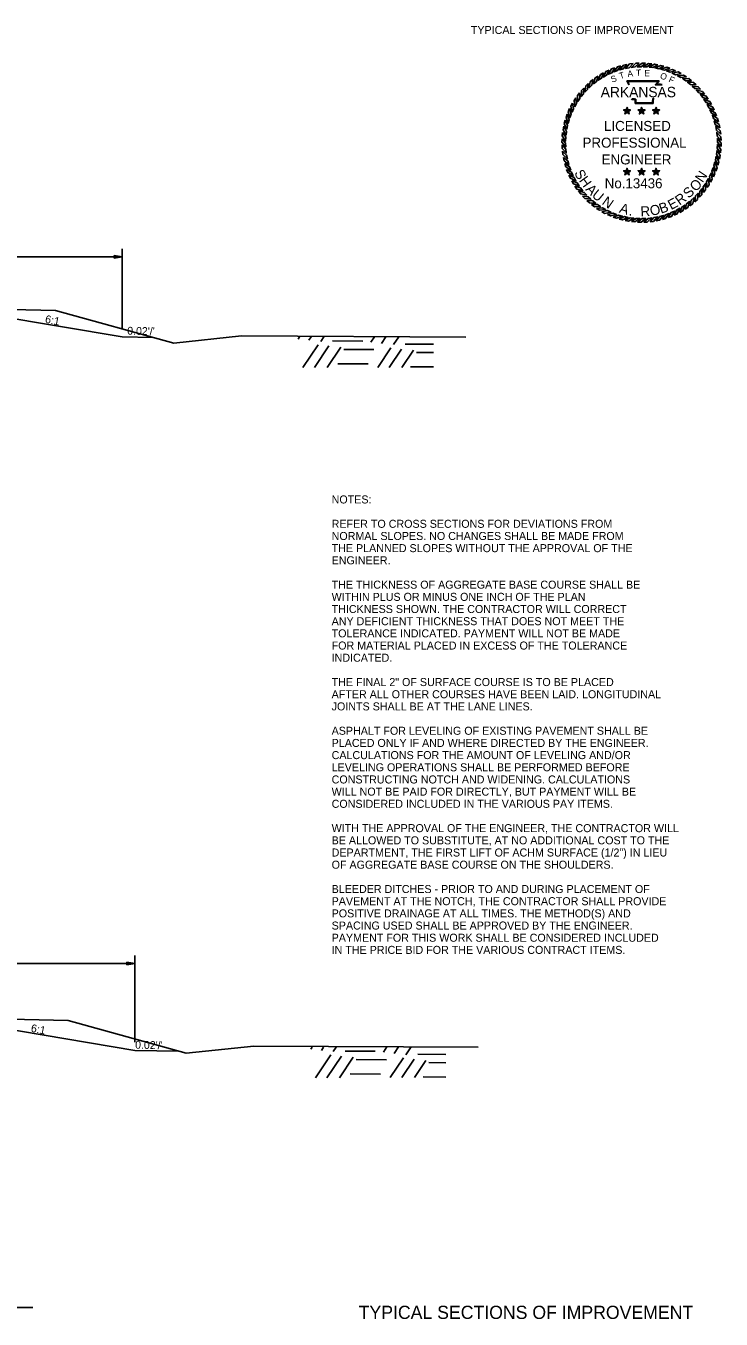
# Model space of a CAD drawing. Extents: x 1398565 to 1398920, y 1968324 to 1968581.
# Drawn here: x 1398667.6 to 1398719.8, y 1968480.4 to 1968577.4 of the extents above; entities that cross this region are included whole.
import ezdxf

# ---------------------------------------------------------------- set-up
doc = ezdxf.new("R2010")
doc.units = 0
for name, color, linetype in [('1', 7, 'Continuous'), ('10', 7, 'Continuous'), ('19', 7, 'Continuous'), ('42', 7, 'Continuous'), ('9', 7, 'Continuous'), ('G-ANNO-SYMB', 7, 'Continuous')]:
    doc.layers.add(name, color=color, linetype=linetype)

msp = doc.modelspace()

# ---------------------------------------------------------------- linework, layer by layer
at = {"layer": '19'}
for p, q in [((1398674.859, 1968554.677), (1398674.859, 1968560.664)), ((1398652.859, 1968560.064), (1398674.859, 1968560.064)), ((1398674.259, 1968559.959), (1398674.259, 1968560.169)), ((1398674.259, 1968560.169), (1398674.859, 1968560.064)), ((1398674.259, 1968560.114), (1398674.699, 1968560.079)), ((1398674.859, 1968560.064), (1398674.259, 1968559.959)), ((1398674.699, 1968560.049), (1398674.259, 1968560.009)), ((1398660.859, 1968556.402), (1398674.859, 1968554.068)), ((1398677.176, 1968554.022), (1398674.859, 1968554.068)), ((1398675.195, 1968506.994), (1398675.195, 1968507.204)), ((1398675.195, 1968507.204), (1398675.795, 1968507.099)), ((1398675.795, 1968501.198), (1398675.795, 1968507.699)), ((1398653.795, 1968507.099), (1398675.795, 1968507.099)), ((1398675.195, 1968507.149), (1398675.635, 1968507.114)), ((1398675.795, 1968507.099), (1398675.195, 1968506.994)), ((1398675.635, 1968507.084), (1398675.195, 1968507.044)), ((1398659.795, 1968503.256), (1398675.795, 1968500.59)), ((1398679.094, 1968500.524), (1398675.795, 1968500.59)), ((1398639.176, 1968481.304), (1398668.156, 1968481.304))]:
    msp.add_line(p, q, dxfattribs=at)
at = {"layer": '42'}
for points in [[(1398652.859, 1968556.515), (1398660.944, 1968556.232), (1398669.859, 1968556.055), (1398678.715, 1968553.595), (1398683.795, 1968554.136), (1398700.612, 1968554.047)], [(1398653.795, 1968503.29), (1398659.88, 1968503.086), (1398670.795, 1968502.83), (1398679.65, 1968500.369), (1398684.731, 1968500.911), (1398701.547, 1968500.822)]]:
    msp.add_lwpolyline(points, dxfattribs=at)
at = {"layer": '9'}
for p, q in [((1398688.049, 1968553.904), (1398688.153, 1968554.058)), ((1398688.847, 1968553.813), (1398689.013, 1968554.06)), ((1398689.737, 1968553.722), (1398689.965, 1968554.061)), ((1398690.627, 1968553.76), (1398692.889, 1968553.746)), ((1398693.501, 1968553.673), (1398693.766, 1968554.068)), ((1398694.298, 1968553.581), (1398694.626, 1968554.069)), ((1398695.188, 1968553.49), (1398695.579, 1968554.071)), ((1398688.399, 1968551.764), (1398689.552, 1968553.48)), ((1398689.258, 1968551.766), (1398690.349, 1968553.389)), ((1398690.211, 1968551.768), (1398691.239, 1968553.298)), ((1398691.462, 1968553.131), (1398693.724, 1968553.116)), ((1398694.012, 1968551.774), (1398695.003, 1968553.249)), ((1398694.872, 1968551.776), (1398695.801, 1968553.157)), ((1398695.824, 1968551.777), (1398696.691, 1968553.066)), ((1398696.078, 1968553.529), (1398698.184, 1968553.515)), ((1398696.913, 1968552.899), (1398698.185, 1968552.891)), ((1398691.019, 1968552.055), (1398693.281, 1968552.04)), ((1398696.47, 1968551.823), (1398698.187, 1968551.812)), ((1398688.985, 1968500.679), (1398689.089, 1968500.833)), ((1398689.782, 1968500.587), (1398689.948, 1968500.834)), ((1398690.673, 1968500.496), (1398690.901, 1968500.836)), ((1398691.562, 1968500.535), (1398693.824, 1968500.52)), ((1398694.436, 1968500.447), (1398694.702, 1968500.842)), ((1398695.234, 1968500.356), (1398695.562, 1968500.844)), ((1398696.124, 1968500.264), (1398696.514, 1968500.846)), ((1398689.334, 1968498.539), (1398690.488, 1968500.255)), ((1398690.194, 1968498.54), (1398691.285, 1968500.163)), ((1398691.146, 1968498.542), (1398692.175, 1968500.072)), ((1398692.398, 1968499.906), (1398694.66, 1968499.891)), ((1398694.948, 1968498.549), (1398695.939, 1968500.023)), ((1398695.807, 1968498.55), (1398696.736, 1968499.932)), ((1398696.76, 1968498.552), (1398697.626, 1968499.84)), ((1398697.014, 1968500.303), (1398699.119, 1968500.29)), ((1398697.849, 1968499.674), (1398699.121, 1968499.666)), ((1398691.955, 1968498.829), (1398694.217, 1968498.815)), ((1398697.406, 1968498.597), (1398699.122, 1968498.586))]:
    msp.add_line(p, q, dxfattribs=at)
at = {"layer": 'G-ANNO-SYMB'}
for points in [[(1398711.35, 1968574.067), (1398711.118, 1968573.957), (1398710.925, 1968573.543), (1398711.168, 1968573.676)], [(1398711.784, 1968574.242), (1398711.545, 1968574.15), (1398711.32, 1968573.752), (1398711.572, 1968573.866)], [(1398712.231, 1968574.382), (1398711.985, 1968574.309), (1398711.73, 1968573.93), (1398711.99, 1968574.024)], [(1398712.688, 1968574.486), (1398712.437, 1968574.433), (1398712.152, 1968574.076), (1398712.42, 1968574.149)], [(1398713.152, 1968574.555), (1398712.897, 1968574.522), (1398712.585, 1968574.187), (1398712.857, 1968574.239)], [(1398713.619, 1968574.586), (1398713.363, 1968574.573), (1398713.026, 1968574.264), (1398713.301, 1968574.295)], [(1398714.087, 1968574.581), (1398713.831, 1968574.589), (1398713.471, 1968574.307), (1398713.748, 1968574.316)], [(1398714.554, 1968574.54), (1398714.299, 1968574.567), (1398713.917, 1968574.315), (1398714.194, 1968574.302)], [(1398715.016, 1968574.461), (1398714.764, 1968574.509), (1398714.364, 1968574.287), (1398714.639, 1968574.252)], [(1398715.47, 1968574.347), (1398715.222, 1968574.414), (1398714.806, 1968574.224), (1398715.078, 1968574.168)], [(1398715.914, 1968574.198), (1398715.672, 1968574.284), (1398715.243, 1968574.127), (1398715.509, 1968574.05)], [(1398716.345, 1968574.014), (1398716.111, 1968574.119), (1398715.67, 1968573.996), (1398715.929, 1968573.898)], [(1398710.146, 1968573.347), (1398709.946, 1968573.186), (1398709.855, 1968572.738), (1398710.06, 1968572.925)], [(1398710.528, 1968573.618), (1398710.316, 1968573.474), (1398710.19, 1968573.034), (1398710.409, 1968573.204)], [(1398710.93, 1968573.859), (1398710.708, 1968573.731), (1398710.547, 1968573.303), (1398710.779, 1968573.455)], [(1398716.76, 1968573.797), (1398716.535, 1968573.92), (1398716.086, 1968573.832), (1398716.337, 1968573.714)], [(1398717.157, 1968573.548), (1398716.942, 1968573.688), (1398716.488, 1968573.636), (1398716.728, 1968573.499)], [(1398717.533, 1968573.268), (1398717.33, 1968573.425), (1398716.873, 1968573.409), (1398717.102, 1968573.253)], [(1398717.886, 1968572.96), (1398717.695, 1968573.132), (1398717.239, 1968573.152), (1398717.455, 1968572.979)], [(1398709.144, 1968572.366), (1398708.987, 1968572.163), (1398709.003, 1968571.706), (1398709.159, 1968571.935)], [(1398709.452, 1968572.719), (1398709.28, 1968572.529), (1398709.26, 1968572.072), (1398709.433, 1968572.288)], [(1398709.787, 1968573.047), (1398709.6, 1968572.871), (1398709.545, 1968572.417), (1398709.734, 1968572.619)], [(1398718.213, 1968572.625), (1398718.037, 1968572.812), (1398717.583, 1968572.868), (1398717.785, 1968572.678)], [(1398718.514, 1968572.266), (1398718.353, 1968572.466), (1398717.905, 1968572.557), (1398718.091, 1968572.352)], [(1398718.785, 1968571.884), (1398718.64, 1968572.096), (1398718.201, 1968572.222), (1398718.371, 1968572.003)], [(1398708.398, 1968571.178), (1398708.294, 1968570.944), (1398708.416, 1968570.503), (1398708.514, 1968570.763)], [(1398708.616, 1968571.593), (1398708.493, 1968571.368), (1398708.58, 1968570.919), (1398708.698, 1968571.17)], [(1398708.865, 1968571.99), (1398708.724, 1968571.775), (1398708.776, 1968571.321), (1398708.913, 1968571.562)], [(1398712.698, 1968570.998), (1398712.76, 1968571.083), (1398712.698, 1968571.271), (1398712.637, 1968571.083)], [(1398713.789, 1968570.998), (1398713.851, 1968571.083), (1398713.789, 1968571.271), (1398713.728, 1968571.083)], [(1398714.88, 1968570.998), (1398714.942, 1968571.083), (1398714.88, 1968571.271), (1398714.819, 1968571.083)], [(1398719.026, 1968571.482), (1398718.898, 1968571.705), (1398718.469, 1968571.865), (1398718.622, 1968571.633)], [(1398719.234, 1968571.062), (1398719.124, 1968571.294), (1398718.709, 1968571.487), (1398718.843, 1968571.245)], [(1398708.065, 1968570.303), (1398707.998, 1968570.056), (1398708.188, 1968569.64), (1398708.244, 1968569.911)], [(1398708.215, 1968570.747), (1398708.128, 1968570.506), (1398708.285, 1968570.076), (1398708.362, 1968570.342)], [(1398712.698, 1968570.998), (1398712.637, 1968571.083), (1398712.439, 1968571.083), (1398712.599, 1968570.966)], [(1398712.698, 1968570.998), (1398712.599, 1968570.966), (1398712.538, 1968570.778), (1398712.698, 1968570.894)], [(1398712.698, 1968570.998), (1398712.798, 1968570.966), (1398712.958, 1968571.083), (1398712.76, 1968571.083)], [(1398712.698, 1968570.998), (1398712.698, 1968570.894), (1398712.859, 1968570.778), (1398712.798, 1968570.966)], [(1398713.789, 1968570.998), (1398713.728, 1968571.083), (1398713.53, 1968571.083), (1398713.69, 1968570.966)], [(1398713.789, 1968570.998), (1398713.69, 1968570.966), (1398713.629, 1968570.778), (1398713.789, 1968570.894)], [(1398713.789, 1968570.998), (1398713.888, 1968570.966), (1398714.049, 1968571.083), (1398713.851, 1968571.083)], [(1398713.789, 1968570.998), (1398713.789, 1968570.894), (1398713.95, 1968570.778), (1398713.888, 1968570.966)], [(1398714.88, 1968570.998), (1398714.819, 1968571.083), (1398714.621, 1968571.083), (1398714.781, 1968570.966)], [(1398714.88, 1968570.998), (1398714.781, 1968570.966), (1398714.72, 1968570.778), (1398714.88, 1968570.894)], [(1398714.88, 1968570.998), (1398714.979, 1968570.966), (1398715.14, 1968571.083), (1398714.942, 1968571.083)], [(1398714.88, 1968570.998), (1398714.88, 1968570.894), (1398715.041, 1968570.778), (1398714.979, 1968570.966)], [(1398719.408, 1968570.628), (1398719.317, 1968570.867), (1398718.919, 1968571.093), (1398719.033, 1968570.84)], [(1398719.548, 1968570.181), (1398719.476, 1968570.427), (1398719.097, 1968570.683), (1398719.191, 1968570.422)], [(1398719.653, 1968569.724), (1398719.6, 1968569.975), (1398719.242, 1968570.26), (1398719.315, 1968569.992)], [(1398707.873, 1968569.387), (1398707.845, 1968569.132), (1398708.098, 1968568.751), (1398708.111, 1968569.028)], [(1398707.951, 1968569.849), (1398707.904, 1968569.597), (1398708.125, 1968569.197), (1398708.16, 1968569.472)], [(1398719.721, 1968569.261), (1398719.688, 1968569.515), (1398719.354, 1968569.827), (1398719.406, 1968569.555)], [(1398719.753, 1968568.793), (1398719.74, 1968569.049), (1398719.431, 1968569.387), (1398719.462, 1968569.111)], [(1398707.831, 1968568.921), (1398707.824, 1968568.664), (1398708.105, 1968568.304), (1398708.096, 1968568.581)], [(1398707.826, 1968568.452), (1398707.839, 1968568.196), (1398708.148, 1968567.859), (1398708.117, 1968568.134)], [(1398719.706, 1968567.858), (1398719.734, 1968568.113), (1398719.481, 1968568.495), (1398719.468, 1968568.218)], [(1398719.748, 1968568.325), (1398719.755, 1968568.581), (1398719.474, 1968568.942), (1398719.482, 1968568.665)], [(1398707.858, 1968567.985), (1398707.891, 1968567.73), (1398708.225, 1968567.419), (1398708.173, 1968567.691)], [(1398707.926, 1968567.521), (1398707.979, 1968567.27), (1398708.337, 1968566.986), (1398708.263, 1968567.253)], [(1398719.514, 1968566.942), (1398719.581, 1968567.19), (1398719.391, 1968567.606), (1398719.335, 1968567.334)], [(1398719.628, 1968567.396), (1398719.675, 1968567.649), (1398719.454, 1968568.048), (1398719.419, 1968567.773)], [(1398708.03, 1968567.065), (1398708.103, 1968566.819), (1398708.482, 1968566.563), (1398708.388, 1968566.824)], [(1398708.17, 1968566.618), (1398708.262, 1968566.378), (1398708.66, 1968566.153), (1398708.546, 1968566.405)], [(1398712.698, 1968566.43), (1398712.637, 1968566.514), (1398712.439, 1968566.514), (1398712.599, 1968566.398)], [(1398712.698, 1968566.43), (1398712.599, 1968566.398), (1398712.538, 1968566.21), (1398712.698, 1968566.326)], [(1398712.698, 1968566.43), (1398712.76, 1968566.514), (1398712.698, 1968566.703), (1398712.637, 1968566.514)], [(1398712.698, 1968566.43), (1398712.798, 1968566.398), (1398712.958, 1968566.514), (1398712.76, 1968566.514)], [(1398712.698, 1968566.43), (1398712.698, 1968566.326), (1398712.859, 1968566.21), (1398712.798, 1968566.398)], [(1398713.789, 1968566.43), (1398713.728, 1968566.514), (1398713.53, 1968566.514), (1398713.69, 1968566.398)], [(1398713.789, 1968566.43), (1398713.69, 1968566.398), (1398713.629, 1968566.21), (1398713.789, 1968566.326)], [(1398713.789, 1968566.43), (1398713.851, 1968566.514), (1398713.789, 1968566.703), (1398713.728, 1968566.514)], [(1398713.789, 1968566.43), (1398713.888, 1968566.398), (1398714.049, 1968566.514), (1398713.851, 1968566.514)], [(1398713.789, 1968566.43), (1398713.789, 1968566.326), (1398713.95, 1968566.21), (1398713.888, 1968566.398)], [(1398714.88, 1968566.43), (1398714.819, 1968566.514), (1398714.621, 1968566.514), (1398714.781, 1968566.398)], [(1398714.88, 1968566.43), (1398714.781, 1968566.398), (1398714.72, 1968566.21), (1398714.88, 1968566.326)], [(1398714.88, 1968566.43), (1398714.942, 1968566.514), (1398714.88, 1968566.703), (1398714.819, 1968566.514)], [(1398714.88, 1968566.43), (1398714.979, 1968566.398), (1398715.14, 1968566.514), (1398714.942, 1968566.514)], [(1398714.88, 1968566.43), (1398714.88, 1968566.326), (1398715.041, 1968566.21), (1398714.979, 1968566.398)], [(1398718.963, 1968565.652), (1398719.086, 1968565.877), (1398718.999, 1968566.326), (1398718.881, 1968566.075)], [(1398719.18, 1968566.067), (1398719.285, 1968566.301), (1398719.163, 1968566.742), (1398719.065, 1968566.483)], [(1398719.364, 1968566.498), (1398719.45, 1968566.74), (1398719.294, 1968567.169), (1398719.217, 1968566.903)], [(1398708.345, 1968566.183), (1398708.455, 1968565.951), (1398708.869, 1968565.758), (1398708.736, 1968566.001)], [(1398708.553, 1968565.763), (1398708.681, 1968565.541), (1398709.109, 1968565.381), (1398708.957, 1968565.612)], [(1398708.794, 1968565.361), (1398708.939, 1968565.15), (1398709.378, 1968565.024), (1398709.208, 1968565.243)], [(1398718.435, 1968564.879), (1398718.591, 1968565.083), (1398718.576, 1968565.54), (1398718.42, 1968565.31)], [(1398718.714, 1968565.255), (1398718.854, 1968565.47), (1398718.803, 1968565.925), (1398718.665, 1968565.684)], [(1398709.065, 1968564.98), (1398709.226, 1968564.78), (1398709.674, 1968564.689), (1398709.488, 1968564.894)], [(1398709.365, 1968564.62), (1398709.542, 1968564.434), (1398709.995, 1968564.378), (1398709.793, 1968564.568)], [(1398717.433, 1968563.898), (1398717.632, 1968564.059), (1398717.724, 1968564.507), (1398717.519, 1968564.321)], [(1398717.792, 1968564.199), (1398717.979, 1968564.375), (1398718.034, 1968564.829), (1398717.845, 1968564.627)], [(1398718.127, 1968564.526), (1398718.299, 1968564.717), (1398718.319, 1968565.174), (1398718.146, 1968564.957)], [(1398709.693, 1968564.285), (1398709.883, 1968564.113), (1398710.34, 1968564.093), (1398710.124, 1968564.267)], [(1398710.046, 1968563.977), (1398710.249, 1968563.821), (1398710.706, 1968563.837), (1398710.477, 1968563.992)], [(1398710.422, 1968563.698), (1398710.637, 1968563.558), (1398711.091, 1968563.61), (1398710.85, 1968563.747)], [(1398710.819, 1968563.449), (1398711.044, 1968563.326), (1398711.493, 1968563.413), (1398711.242, 1968563.531)], [(1398715.794, 1968563.004), (1398716.034, 1968563.095), (1398716.259, 1968563.493), (1398716.007, 1968563.379)], [(1398716.229, 1968563.178), (1398716.461, 1968563.288), (1398716.654, 1968563.703), (1398716.411, 1968563.569)], [(1398716.649, 1968563.387), (1398716.871, 1968563.514), (1398717.031, 1968563.943), (1398716.8, 1968563.79)], [(1398717.051, 1968563.627), (1398717.262, 1968563.772), (1398717.389, 1968564.212), (1398717.17, 1968564.042)], [(1398711.234, 1968563.232), (1398711.468, 1968563.127), (1398711.909, 1968563.249), (1398711.649, 1968563.347)], [(1398711.665, 1968563.048), (1398711.906, 1968562.962), (1398712.336, 1968563.118), (1398712.07, 1968563.195)], [(1398712.109, 1968562.898), (1398712.356, 1968562.831), (1398712.772, 1968563.021), (1398712.501, 1968563.077)], [(1398712.563, 1968562.784), (1398712.815, 1968562.737), (1398713.215, 1968562.959), (1398712.94, 1968562.993)], [(1398713.025, 1968562.706), (1398713.28, 1968562.679), (1398713.661, 1968562.931), (1398713.384, 1968562.944)], [(1398713.491, 1968562.664), (1398713.748, 1968562.657), (1398714.108, 1968562.938), (1398713.831, 1968562.93)], [(1398713.96, 1968562.659), (1398714.216, 1968562.672), (1398714.553, 1968562.981), (1398714.278, 1968562.951)], [(1398714.427, 1968562.691), (1398714.682, 1968562.724), (1398714.994, 1968563.058), (1398714.721, 1968563.006)], [(1398714.891, 1968562.759), (1398715.142, 1968562.812), (1398715.426, 1968563.17), (1398715.159, 1968563.097)], [(1398715.347, 1968562.864), (1398715.594, 1968562.936), (1398715.849, 1968563.315), (1398715.588, 1968563.221)]]:
    msp.add_lwpolyline(points, close=True, dxfattribs=at)
for points in [[(1398712.834, 1968572.953), (1398712.695, 1968573.254), (1398715.101, 1968573.255), (1398714.9, 1968573.003), (1398715.063, 1968573.005), (1398715.2, 1968573.007), (1398715.336, 1968572.992)], [(1398712.868, 1968572.969), (1398712.754, 1968573.216), (1398715.022, 1968573.217), (1398714.82, 1968572.964), (1398715.064, 1968572.967), (1398715.198, 1968572.968), (1398715.332, 1968572.954)], [(1398714.722, 1968571.944), (1398714.681, 1968571.911), (1398714.667, 1968571.861), (1398714.653, 1968571.736), (1398714.653, 1968571.57), (1398713.31, 1968571.57), (1398713.31, 1968571.794), (1398713.31, 1968571.844), (1398713.256, 1968571.861), (1398713.065, 1968571.861), (1398713.031, 1968571.913)], [(1398714.698, 1968571.974), (1398714.647, 1968571.933), (1398714.629, 1968571.868), (1398714.615, 1968571.738), (1398714.615, 1968571.608), (1398713.348, 1968571.608), (1398713.348, 1968571.794), (1398713.348, 1968571.873), (1398713.261, 1968571.899), (1398713.085, 1968571.899), (1398713.062, 1968571.934)]]:
    msp.add_lwpolyline(points, dxfattribs=at)

# ---------------------------------------------------------------- texts
at = {"layer": '1'}
msp.add_text('TYPICAL SECTIONS OF IMPROVEMENT', height=0.6, dxfattribs=at).set_placement((1398700.991, 1968576.769))
at = {"layer": '10'}
for p in [(1398669.036, 1968555.133), (1398667.971, 1968501.988)]:
    msp.add_text('6:1', height=0.59, rotation=348.76163, dxfattribs=at).set_placement(p)
at = {"layer": '19'}
for p in [(1398675.227, 1968554.234), (1398675.817, 1968500.716)]:
    msp.add_text("0.02'/'", height=0.59, rotation=358.85424, dxfattribs=at).set_placement(p)
for s, height, p in [('NOTES:', 0.6, (1398690.554, 1968541.581)), ('REFER TO CROSS SECTIONS FOR DEVIATIONS FROM', 0.6, (1398690.554, 1968539.756)), ('NORMAL SLOPES. NO CHANGES SHALL BE MADE FROM ', 0.6, (1398690.554, 1968538.844)), ('THE PLANNED SLOPES WITHOUT THE APPROVAL OF THE', 0.6, (1398690.554, 1968537.931)), ('ENGINEER.', 0.6, (1398690.554, 1968537.019)), ('THE THICKNESS OF AGGREGATE BASE COURSE SHALL BE', 0.6, (1398690.554, 1968535.194)), ('WITHIN PLUS OR MINUS ONE INCH OF THE PLAN ', 0.6, (1398690.554, 1968534.281)), ('THICKNESS SHOWN. THE CONTRACTOR WILL CORRECT', 0.6, (1398690.554, 1968533.369)), ('ANY DEFICIENT THICKNESS THAT DOES NOT MEET THE', 0.6, (1398690.554, 1968532.456)), ('TOLERANCE INDICATED. PAYMENT WILL NOT BE MADE', 0.6, (1398690.554, 1968531.544)), ('FOR MATERIAL PLACED IN EXCESS OF THE TOLERANCE', 0.6, (1398690.554, 1968530.631)), ('INDICATED.', 0.6, (1398690.554, 1968529.719)), ('THE FINAL 2" OF SURFACE COURSE IS TO BE PLACED', 0.6, (1398690.554, 1968527.894)), ('AFTER ALL OTHER COURSES HAVE BEEN LAID. LONGITUDINAL', 0.6, (1398690.554, 1968526.981)), ('JOINTS SHALL BE AT THE LANE LINES.', 0.6, (1398690.554, 1968526.069)), ('ASPHALT FOR LEVELING OF EXISTING PAVEMENT SHALL BE', 0.6, (1398690.554, 1968524.244)), ('PLACED ONLY IF AND WHERE DIRECTED BY THE ENGINEER.', 0.6, (1398690.554, 1968523.331)), ('CALCULATIONS FOR THE AMOUNT OF LEVELING AND/OR', 0.6, (1398690.554, 1968522.419)), ('LEVELING OPERATIONS SHALL BE PERFORMED BEFORE ', 0.6, (1398690.554, 1968521.506)), ('CONSTRUCTING NOTCH AND WIDENING. CALCULATIONS', 0.6, (1398690.554, 1968520.594)), ('WILL NOT BE PAID FOR DIRECTLY, BUT PAYMENT WILL BE', 0.6, (1398690.554, 1968519.681)), ('CONSIDERED INCLUDED IN THE VARIOUS PAY ITEMS.', 0.6, (1398690.554, 1968518.769)), ('WITH THE APPROVAL OF THE ENGINEER, THE CONTRACTOR WILL', 0.6, (1398690.554, 1968516.944)), ('BE ALLOWED TO SUBSTITUTE, AT NO ADDITIONAL COST TO THE', 0.6, (1398690.554, 1968516.031)), ('DEPARTMENT, THE FIRST LIFT OF ACHM SURFACE (1/2") IN LIEU', 0.6, (1398690.554, 1968515.119)), ('OF AGGREGATE BASE COURSE ON THE SHOULDERS.', 0.6, (1398690.554, 1968514.206)), ('BLEEDER DITCHES - PRIOR TO AND DURING PLACEMENT OF', 0.6, (1398690.554, 1968512.381)), ('PAVEMENT AT THE NOTCH, THE CONTRACTOR SHALL PROVIDE', 0.6, (1398690.554, 1968511.469)), ('POSITIVE DRAINAGE AT ALL TIMES. THE METHOD(S) AND', 0.6, (1398690.554, 1968510.556)), ('SPACING USED SHALL BE APPROVED BY THE ENGINEER.', 0.6, (1398690.554, 1968509.644)), ('PAYMENT FOR THIS WORK SHALL BE CONSIDERED INCLUDED', 0.6, (1398690.554, 1968508.731)), ('IN THE PRICE BID FOR THE VARIOUS CONTRACT ITEMS.', 0.6, (1398690.554, 1968507.819)), ('TYPICAL SECTIONS OF IMPROVEMENT', 0.98999, (1398692.58, 1968480.457))]:
    msp.add_text(s, height=height, dxfattribs=at).set_placement(p)
at = {"layer": 'G-ANNO-SYMB'}
for s, height, rotation, p in [('T', 0.475, 1.47887, (1398713.373, 1968573.626)), ('E', 0.475, 356.67203, (1398713.981, 1968573.612)), ('S', 0.475, 19.77256, (1398711.58, 1968573.111)), ('T', 0.475, 16.90148, (1398712.184, 1968573.382)), ('A', 0.475, 8.67877, (1398712.76, 1968573.532)), ('O', 0.475, 341.2218, (1398715.133, 1968573.449)), ('F', 0.475, 335.36282, (1398715.773, 1968573.199)), ('ARKANSAS', 0.7747, 360, (1398710.727, 1968572.031)), ('LICENSED', 0.75, 360, (1398710.968, 1968569.502)), ('PROFESSIONAL', 0.75, 360, (1398709.361, 1968568.248)), ('ENGINEER', 0.75, 360, (1398710.789, 1968566.993)), ('S', 0.75, 298.16364, (1398708.721, 1968566.363)), ('N', 0.75, 56.10067, (1398718.363, 1968565.579)), ('H', 0.75, 305.61905, (1398709.063, 1968565.775)), ('A', 0.75, 313.44722, (1398709.54, 1968565.091)), ('No.13436', 0.747, 360, (1398711.026, 1968565.206)), ('O', 0.75, 44.77573, (1398717.843, 1968564.904)), ('U', 0.75, 320.90262, (1398710.007, 1968564.602)), ('N', 0.75, 324.93262, (1398710.763, 1968564.043)), ('E', 0.75, 27.83149, (1398716.004, 1968563.565)), ('R', 0.75, 35.65967, (1398716.638, 1968563.897)), ('S', 0.75, 43.48784, (1398717.327, 1968564.407)), ('A', 0.75, 343.09908, (1398712.07, 1968563.4)), ('R', 0.75, 3.22866, (1398713.727, 1968563.086)), ('O', 0.75, 11.42961, (1398714.494, 1968563.135)), ('B', 0.75, 18.88501, (1398715.246, 1968563.294)), ('.', 0.75, 351.30002, (1398712.807, 1968563.181))]:
    msp.add_text(s, height=height, rotation=rotation, dxfattribs=at).set_placement(p)

doc.saveas('drawing.dxf')
